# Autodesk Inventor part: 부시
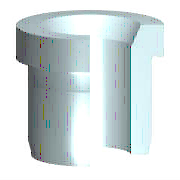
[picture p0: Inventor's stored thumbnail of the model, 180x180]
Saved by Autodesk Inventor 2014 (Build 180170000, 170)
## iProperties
IsCustomPart: 1
Created: 2009-02
Part Number: 부시
Material: 강, 연강
Description: 압력 맞춤 부시 - 머리 있는 유형
Document SubType Name: Modeling
Standard: ISO 4247
Designer: KYOUNG IL JANG
Standard Revision: 1판 1977-12-15
Standards Organization: ISO
Language: ko-KR
Size Designation: 15
Categories: <MemberInstance><Categories><Category DisplayName="기타 부품" InternalName="5aa15e00-363f-49f2-933f-16f664388e3f" Mnemonic="OTHER"><Category DisplayName="드릴 부싱" Int
Density: 1 g/cm^3
Appearance: 강철
Author: KYOUNG IL JANG
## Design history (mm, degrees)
revolve "본체" stored, may be unused: angle "d12" = 90 deg
body "Solid1"
chamfer "모따기1" distance "d13" = 2 (= KAH); stored, may be unused: angle "d14" = 30 deg (= SEWI), second distance "d19" = 2 (= KAH)
chamfer "모따기2" distance "d15" = 1.5 (= PHH); stored, may be unused: angle "d16" = 15 deg (= ANG), second distance "d20" = 1.5 (= PHH)
sketch "스케치1"
  geometry: L1 (2.5, 11)-(24, 11); L2 (24, 11)-(24, 6); L3 (24, 6)-(-4, 6); L4 (-4, 6)-(-4, 13); L5 (-4, 13)-(0, 13); L6 (0, 13)-(0, 12.304); L7 (-2.619, 0)-(24, 0); L8 (0, 12.304)-(-0.187, 11.425); L9 (2.5, 11)-(1.457, 10.72); L10 (0.4, 10.7)-(1.301, 10.7); L11 (-6.4, 0)-(10.4, 0) reference; L12 (0, -2.2)-(0, 13.2) reference; A1 r 0.6 centre (1.301, 11.3) between (1.301, 10.7) and (1.457, 10.72); A2 r 0.6 centre (0.4, 11.3) between (-0.187, 11.425) and (0.4, 10.7)
  constraints: 20 end point, 5 parallel, 4 point on circle, 4 tangent, 2 centre point, 2 collinear, 2 perpendicular, 1 horizontal, 1 point on line
  dimensions: "d0" = 15 deg angle of L1 L9; "d1" = 12 deg angle of L6 L8; "d2" = 0.6 radius of A2 (= FSRR); "d3" = 0.6 radius of A1 (= FSRR); "d4" = 0.3 distance between parallel lines of L1 L10 (= FST1); "d5" = 0.2 distance edge to line of A2 L6 (= FST2); "d6" = 2.5 distance from line of L1.start L6 (= FSB); "d7" = 12 diameter of L3 L7 (= NND); "d8" = 22 diameter of L1 L7 (= SD2); "d9" = 28 distance between parallel lines of L2 L4 (= NLG); "d10" = 4 distance of L4.end L5.end (= KOH); "d11" = 26 diameter of L5 L7 (= KOD)
other parameters: "NLG" = 28 [user parameter; used in 1 equation term], "NND" = 12 [user parameter; used in 1 equation term], "KOH" = 4 [user parameter; used in 1 equation term], "KOD" = 26 [user parameter; used in 1 equation term], "KAH" = 2 [user parameter; used in 2 equation terms], "SEWI" = 30 deg [user parameter; used in 1 equation term], "ANG" = 15 deg [user parameter; used in 1 equation term], "PHH" = 1.5 [user parameter; used in 2 equation terms], "FST1" = 0.3 [user parameter; used in 1 equation term], "FST2" = 0.2 [user parameter; used in 1 equation term], "FSB" = 2.5 [user parameter; used in 1 equation term], "FSRR" = 0.6 [user parameter; used in 2 equation terms], "SD2" = 22 [user parameter; used in 1 equation term], "d17" = 0, "d18" = 0, "NNDMIN" = 12 [user parameter], "FSH" = 2.1 [user parameter], "NNDMAX" = 15 [user parameter]
